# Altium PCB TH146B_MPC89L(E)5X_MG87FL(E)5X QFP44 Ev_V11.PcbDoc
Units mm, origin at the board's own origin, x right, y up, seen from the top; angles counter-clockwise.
Board outline 72.39 x 53.59 mm, 2 copper layers (Top Layer, Bottom Layer); 46 components, 63 nets, 266 pads, 114 vias.
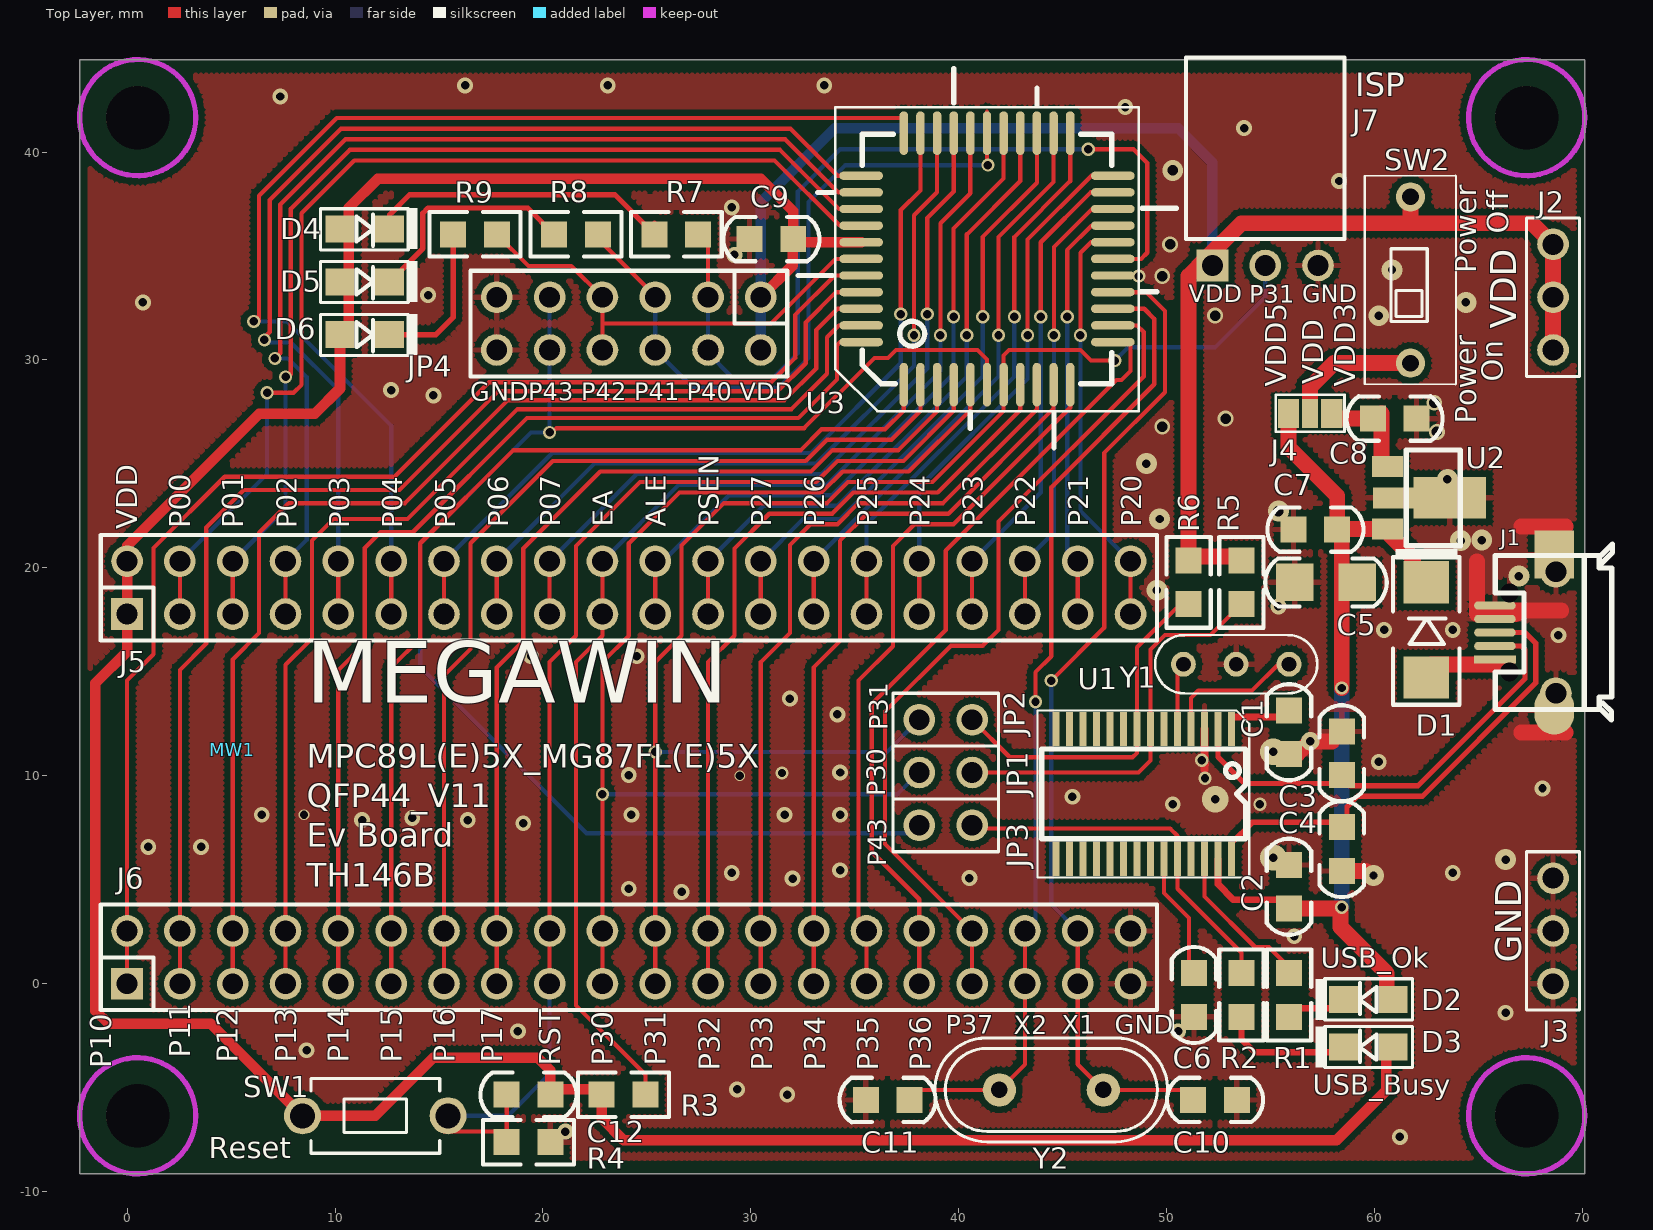
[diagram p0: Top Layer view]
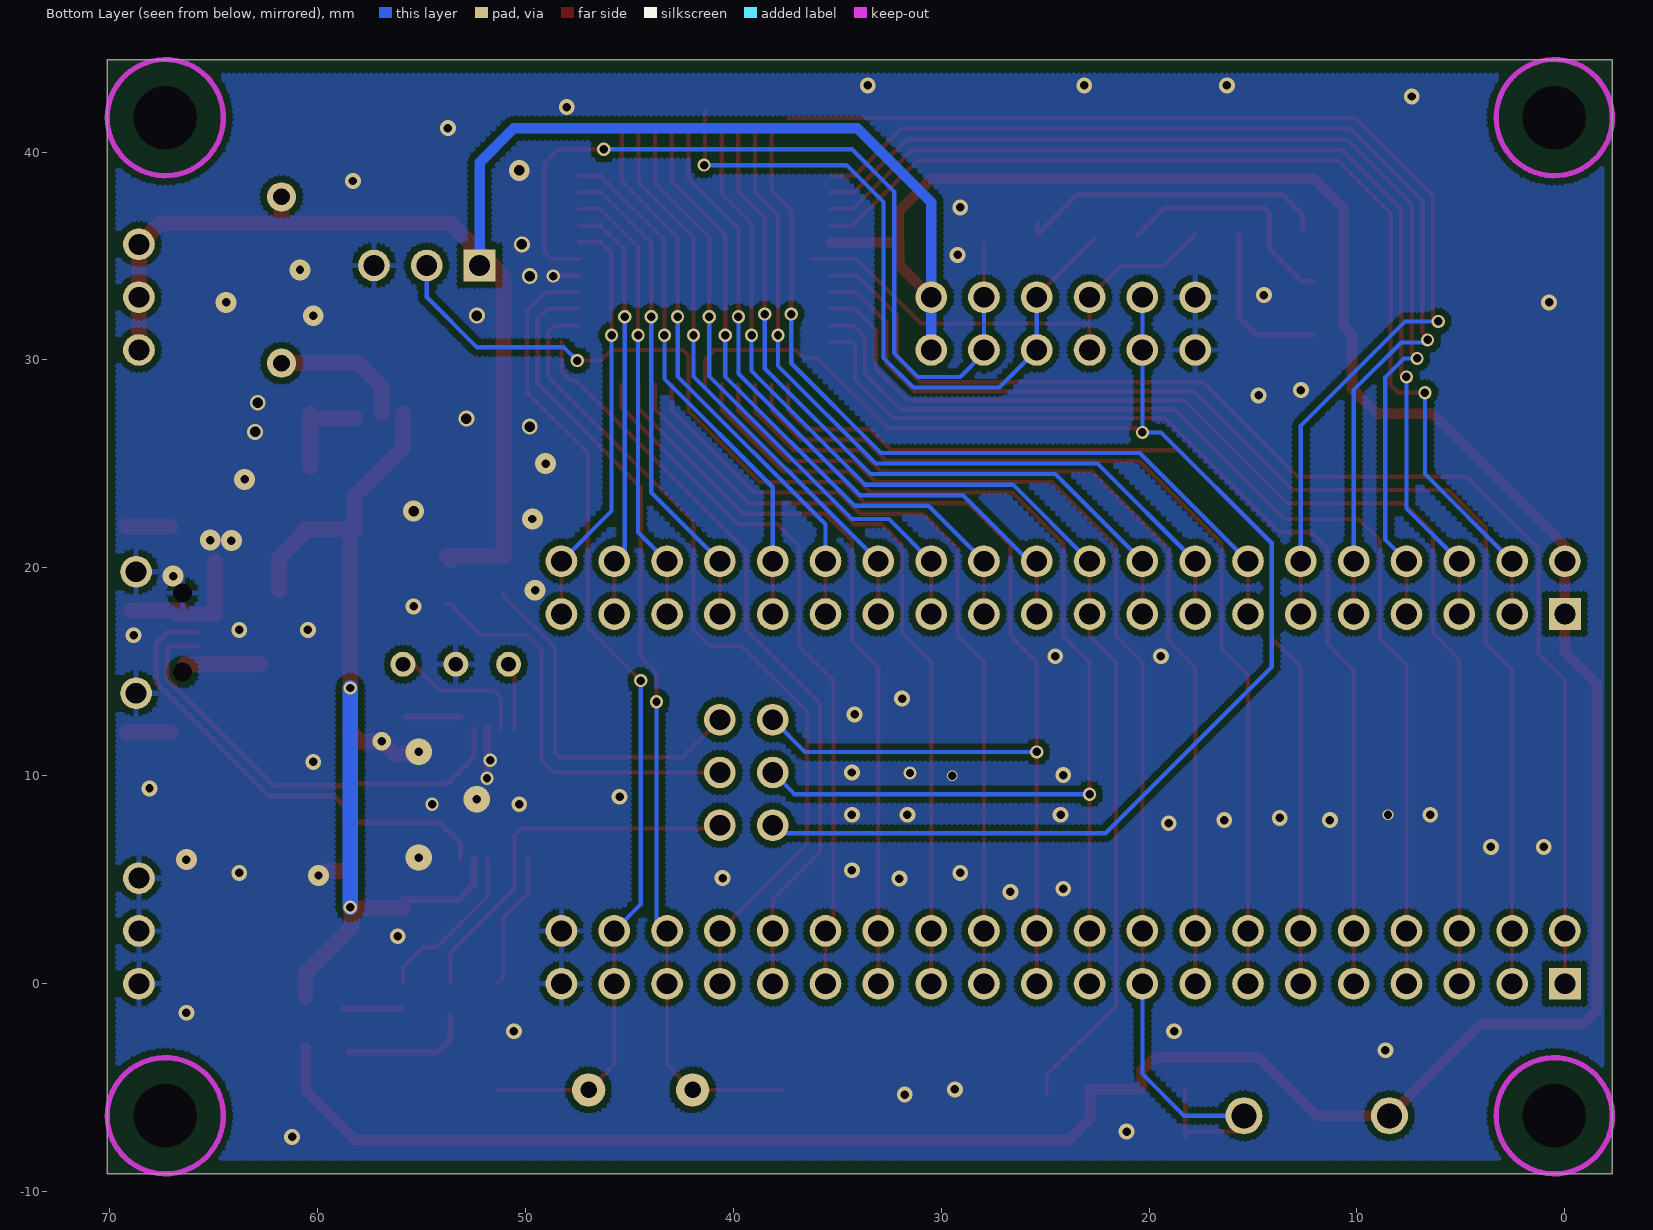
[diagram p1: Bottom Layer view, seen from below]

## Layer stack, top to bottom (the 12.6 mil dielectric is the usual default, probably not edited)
Top Layer: signal copper 0.0356
Dielectric: dielectric 0.32, FR-4, Dk 4.8
Bottom Layer: signal copper 0.0356

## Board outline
-2.286,-9.144 70.104,-9.144 70.104,44.45 -2.286,44.45

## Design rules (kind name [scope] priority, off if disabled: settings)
Clearance 12 [All] p1 off: gap=0.305
Clearance 10 [All] p2 off: gap=0.254
Clearance 6 [All] p3: gap=0.152
ComponentClearance [All] p1 off: gap=0.254 collisioncheckmode=3 verticalgap=0.254 showdistances=FALSE
HoleSize [All] p1: absolutevalues=TRUE maxlimit=12.7 minlimit=0.025 maxpercent=80.000 minpercent=20.000
MinimumSolderMaskSliver [All] p1 off: minsoldermaskwidth=0.254
PolygonConnect VIA [ISVIA] p1: connectstyle=Direct reliefconductorwidth=0.254 reliefentries=4 polygonreliefangle="90 Angle"
PolygonConnect [All] p2: connectstyle=Relief reliefconductorwidth=0.254 reliefentries=4 polygonreliefangle="90 Angle"
RoomDefinition "TH146B_MPC89L(E)5X_MG87FL(E)5X QFP44 Ev_V10" [InComponentClass('TH146B_MPC89L(E)5X_MG87FL(E)5X QFP44 Ev_V10')] p1: confinementstyle=ConfineIn formatcopy=TRUE lockcomponents=FALSE outline -8.636,-13.208 74.549,-13.208 74.549,49.276 -8.636,49.276
RoutingVias [All] p1: holewidth=0.406 width=0.635 viastyle="Through Hole" minholewidth=0.406 minwidth=0.61 maxholewidth=0.711 maxwidth=1.27
SilkToSilkClearance [All] p1 off: silktosilkclearance=0.254
SilkscreenOverComponentPads [All] p1 off: minsilkscreentomaskgap=0.254
SolderMaskExpansion [All] p1 off: expansion=0.102
Width [All] p1: maxlimit=5.08 minlimit=0.152 preferedwidth=0.254
23 further rules are at their usual default settings.

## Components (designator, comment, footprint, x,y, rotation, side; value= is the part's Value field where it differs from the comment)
C1 "4.7uF" 0805C 55.88,12.099 r270 top
C2 "0.1uF" 0805C 55.88,4.665 r270 top
C3 "15pF" 0805C 58.42,11.083 r90 top
C4 "15pF" 0805C 58.42,6.477 r270 top
C5 "4.7uF" 1206C 57.658,19.304 r180 top
C6 "0.1uF" 0805C 51.308,-0.542 r90 top
C7 "0.1uF" 0805C 57.15,21.844 r180 top
C8 "4.7uF" 0805C 60.96,27.178 r0 top
C9 "0.1uF" 0805C 30.988,35.814 r180 top
C10 "30p" 0805C 52.324,-5.588 r0 top
C11 "30p" 0805C 36.576,-5.588 r180 top
C12 "1u" 0805C 19.304,-5.334 r180 top
D1 "1N5817" D5817_SMD_1 62.484,17.018 r270 top
D2 "Yellow" 0805D 59.69,-0.762 r180 top
D3 "RED" 0805D 59.69,-3.048 r180 top
D4 "Green" 0805D 11.43,36.297 r0 top
D5 "RED" 0805D 11.43,33.757 r0 top
D6 "Green" 0805D 11.43,31.217 r0 top
J1 "Micro USB母座" JACK_USB_SMD290X220P065 65.786,16.891 r180 top
J2 "*" PS3P254 68.58,30.48 r90 top
J3 "*" PS3P254 68.58,0 r90 top
J4 "*" JUMP3_SMD 56.896,27.432 r0 top
J5 "CON40A" PS20X2P254 0,17.78 r0 top locked
J6 "CON40A" PS20X2P254 0,0 r0 top
J7 "*" PS3P254f_90 52.197,34.544 r0 top
JP1 "JUMPER2" PS2P254 38.1,10.16 r0 top
JP2 "JUMPER2" PS2P254 38.1,12.7 r0 top
JP3 "JUMPER2" PS2P254 38.1,7.62 r0 top
JP4 "CON6X2" PS6X2P254 30.48,33.02 r180 top
MW1 "MW-A4" MEGAWIN_T 5.059,11.253 r0 top
R1 "1K" 0805R 55.88,-0.542 r270 top
R2 "1K" 0805R 53.594,-0.542 r270 top
R3 "4.7K" 0805R 23.876,-5.334 r0 top
R4 "47K" 0805R 19.304,-7.62 r180 top
R5 "4.7K" 0805R 53.594,19.304 r270 top
R6 "4.7K" 0805R 51.054,19.304 r270 top
R7 "1K" 0805R 26.416,36.043 r180 top
R8 "1K" 0805R 21.59,36.043 r180 top
R9 "1K" 0805R 16.73,36.043 r180 top
SW1 "SW TACT-SPST" SW_T_2P 11.938,-6.35 r180 top
SW2 "-" DIP2_SW 61.722,29.846 r90 top
U1 "MA101_TSSOP28" TSSOP28_170P065 48.891,9.132 r180 top
U2 "AIC1734-33(SOT-89)" SOT89 60.614,23.368 r270 top
U3 "MPC89E53(44-QFP)" QFP44_10X10P080 37.356,28.812 r90 top
Y1 "6MHz" X3P 55.88,15.367 r180 top
Y2 "22.1184MHz" X49U 44.45,-5.105 r180 top

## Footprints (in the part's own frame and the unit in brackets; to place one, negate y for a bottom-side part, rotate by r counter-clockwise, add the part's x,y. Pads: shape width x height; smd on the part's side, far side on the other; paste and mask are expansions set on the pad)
0805C [mm]
  rect 1.25x1.25 smd: 1(-1.05,0) 2(1.05,0)
  silkscreen extent -2.31,-1.07 2.31,1.07
0805D [mm]
  rect 1.4x1.3 smd: 1(-1.192,0) 2(1.192,0)
  silkscreen extent -2.12,-1 2.53,0.98
0805R [mm]
  rect 1.25x1.25 smd: 1(-1.05,0) 2(1.05,0)
  silkscreen extent -2.18,-1.07 2.18,1.07
1206C [mm]
  rect 1.8x1.8 smd: 1(-1.5,0) 2(1.5,0)
  silkscreen extent -2.92,-1.15 2.92,1.16
D5817_SMD_1 [mil]
  rect 80x86.61 smd: 1(90,0) 2(-90,0)
  silkscreen extent -153,-63 142,63
DIP2_SW [mm]
  round 1.4 hole 0.8: 1(0,0) 2(8,0)
  silkscreen extent -1.02,-2.2 9.02,2.2
JACK_USB_SMD290X220P065 [mm]
  rect 1.9x1.8 on Mech2: 0(-2.85,-1.15) 0(-2.85,1.15)
  round 0.8 hole 0.9 unplated: 1(-0.7,1.9) 5(-0.7,-1.9)
  rect 2x0.4 smd: 1(0,1.3)
  oval 2x0.4 smd: 2(0,0.65) 3(0,0) 4(0,-0.65) 5(0,-1.3)
  round 1.524 hole 1: 5(-2.931,2.921) 5(-2.931,-2.921)
  oval 1.9x2.3 smd: 5(-2.85,3.75)
  rect 1.9x2.3 smd: 5(-2.85,-3.75)
  silkscreen extent -5.65,-4.25 -0.01,4.2
JUMP3_SMD [mil]
  rect 40x55 smd: 1(-41,0) 3(41,0)
  rect 30x55 smd: 2(0,0)
  silkscreen extent -65,-35 65,35
MEGAWIN_T [mm]
PS2P254 [mil]
  round 60 hole 39.37: 1(0,0) 2(100,0)
  silkscreen extent -50,-50 150,50
PS3P254 [mil]
  round 60 hole 39.37: 1(0,0) 2(100,0) 3(200,0)
  silkscreen extent -50,-50 250,50
PS3P254f_90 [mil]
  rect 60x60 hole 39.37: 1(0,0)
  round 60 hole 39.37: 2(100,0) 3(200,0)
  silkscreen extent -50,50 250,394
PS6X2P254 [mil]
  round 60 hole 39.37: 1(0,0) 2(0,100) 3(100,0) 4(100,100) 5(200,0) 6(200,100) 7(300,0) 8(300,100) 9(400,0) 10(400,100) 11(500,0) 12(500,100)
  silkscreen extent -50,-50 550,150
PS20X2P254 [mil]
  rect 60x60 hole 39.37: 1(0,0)
  round 60 hole 39.37: 2(0,100) 3(100,0) 4(100,100) 5(200,0) 6(200,100) 7(300,0) 8(300,100) 9(400,0) 10(400,100) 11(500,0) 12(500,100) 13(600,0) 14(600,100) 15(700,0) 16(700,100) 17(800,0) 18(800,100) 19(900,0) 20(900,100) 21(1000,0) 22(1000,100) 23(1100,0) 24(1100,100) 25(1200,0) 26(1200,100) 27(1300,0) 28(1300,100) 29(1400,0) 30(1400,100) 31(1500,0) 32(1500,100) 33(1600,0) 34(1600,100) 35(1700,0) 36(1700,100) 37(1800,0) 38(1800,100) 39(1900,0) 40(1900,100)
  silkscreen extent -50,-50 1950,150
QFP44_10X10P080 [mm]
  oval 2.1x0.406 smd: 1(0,0) 2(0,-0.8) 3(0,-1.6) 4(0,-2.4) 5(0,-3.2) 6(0,-4) 7(0,-4.8) 8(0,-5.6) 9(0,-6.4) 10(0,-7.2) 11(0,-8) 23(12.1,-8) 24(12.1,-7.2) 25(12.1,-6.4) 26(12.1,-5.6) 27(12.1,-4.8) 28(12.1,-4) 29(12.1,-3.2) 30(12.1,-2.4) 31(12.1,-1.6) 32(12.1,-0.8) 33(12.1,0)
  oval 0.406x2.1 smd: 12(2.05,-10.05) 13(2.85,-10.05) 14(3.65,-10.05) 15(4.45,-10.05) 16(5.25,-10.05) 17(6.05,-10.05) 18(6.85,-10.05) 19(7.65,-10.05) 20(8.45,-10.05) 21(9.25,-10.05) 22(10.05,-10.05) 34(10.05,2.05) 35(9.25,2.05) 36(8.45,2.05) 37(7.65,2.05) 38(6.85,2.05) 39(6.05,2.05) 40(5.25,2.05) 41(4.45,2.05) 42(3.65,2.05) 43(2.85,2.05) 44(2.05,2.05)
  silkscreen extent -3.04,-13.12 15.19,5.08
SOT89 [mm]
  rect 1.016x1.5 smd: 1(-1.5,0) 3(1.5,0)
  rect 2x3.5 smd: 2(0,3)
  rect 1.016x2.6 smd: 2(0,0.6)
  silkscreen extent -2.3,0.9 2.3,3.5
SW_T_2P [mm]
  round 1.778 hole 1.2: 1(-3.5,0) 2(3.5,0)
  silkscreen extent -3.1,-1.8 3.1,1.8
TSSOP28_170P065 [mil]
  rect 13x65 smd: 1(-166.34,-123) 2(-140.75,-123) 3(-115.16,-123) 4(-89.57,-123) 5(-63.98,-123) 6(-38.39,-123) 7(-12.79,-123) 8(12.8,-123) 9(38.39,-123) 10(63.98,-123) 11(89.57,-123) 12(115.16,-123) 13(140.75,-123) 14(166.34,-123) 15(166.34,123) 16(140.75,123) 17(115.16,123) 18(89.57,123) 19(63.98,123) 20(38.39,123) 21(12.8,123) 22(-12.79,123) 23(-38.39,123) 24(-63.98,123) 25(-89.57,123) 26(-115.16,123) 27(-140.75,123) 28(-166.34,123)
  silkscreen extent -200,-158 201,158
X3P [mm]
  round 1.2 hole 0.711: 1(0,0) 2(5.08,0) 3(2.54,0)
  silkscreen extent -1.36,-1.4 6.44,1.4
X49U [mm]
  round 1.6 hole 0.8: 1(-2.5,0) 2(2.5,0)
  silkscreen extent -5.6,-2.5 5.6,2.5

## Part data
C1 C5 C8: library part CAP
C2 C3 C4 C6 C7 C9: library part "CAP NP"
C10 C11: library part "C NP"
C12: library part C
D1: library part DIODE_ZD, "Schottky Diode"
D2 D3 D4 D5 D6: library part LED
J1: library part CON5, "Connector"
J2 J3 J4 J7: library part CON3
R1 R2 R5 R6 R7 R8 R9: library part R_Dup1
R3 R4: library part R
SW2: library part SW-2
U2: library part AIC1734-33(SOT-89)_0
U3: library part MPC89L53(44-QFP)
Y1: library part CRYSTAL_RC
Y2: library part CRYSTAL

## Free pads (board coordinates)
  round 3 hole 3.048 unplated: 0(0.508,-6.35) 0(0.508,41.656) 0(67.31,-6.35) 0(67.31,41.656)

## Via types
v1: diameter 0.762, hole 0.406, Top Layer to Bottom Layer, tented both sides, 53 vias
v2: diameter 0.635, hole 0.406, Top Layer to Bottom Layer, tented both sides, 34 vias
v3: diameter 1, hole 0.406, Top Layer to Bottom Layer, tented both sides, 11 vias
v4: diameter 0.762, hole 0.508, Top Layer to Bottom Layer, tented both sides, 7 vias
v5: diameter 1.27, hole 0.406, Top Layer to Bottom Layer, tented both sides, 3 vias
v6: diameter 1, hole 0.508, Top Layer to Bottom Layer, tented both sides, 2 vias
v7: diameter 0.508, hole 0.406, Top Layer to Bottom Layer, tented both sides, 2 vias
v8: diameter 1.016, hole 0.406, Top Layer to Bottom Layer, tented both sides, 1 vias
v9: diameter 0.889, hole 0.406, Top Layer to Bottom Layer, tented both sides, 1 vias

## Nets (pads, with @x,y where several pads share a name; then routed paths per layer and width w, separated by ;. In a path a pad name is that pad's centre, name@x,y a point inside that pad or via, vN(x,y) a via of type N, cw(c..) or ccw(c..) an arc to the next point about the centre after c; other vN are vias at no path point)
ALE: J5.21 J5.22 U3.27 | length 33.2
  Top Layer w0.203: J5.21 J5.22 ; v2(39.751,32.08) 39.751,36.322 42.156,38.727 U3.27
  Bottom Layer w0.203: J5.22 25.781,20.32 28.956,23.495 33.909,23.495 39.751,29.337 v2(39.751,32.08)
D+: C4.1 J1.3 U1.28 | length 22.6
  Top Layer w0.254: U1.28 53.116,6.761 54.119,7.764 C4.1@58.42,7.764 ; C4.1@58.674,8.001 58.674,8.509 59.182,9.017 62.299,9.017 67.742,14.46 67.742,16.381 67.232,16.891 J1.3
D-: C3.1 J1.2 U1.2 | length 21.3
  Top Layer w0.254: U1.2 52.466,10.907 53.737,9.636 C3.1@58.42,9.636 ; C3.1@58.801,9.525 62.089,9.525 67.234,14.67 67.234,16.074 67.067,16.241 J1.2
GND_POWER: C1.2 C2.1 C3.2 C4.2 C5.2 C6.1 C7.2 C8.2 C9.2 C10.2 C11.2 J1.4 J1.5 J3.1 J3.2 J3.3 J6.39 J6.40 J7.3 JP4.11 JP4.12 R4.1 U1.3 U2.2 U3.16 Y1.3 | length 18.4
  Top Layer w0.254: U3.16 48.633,34.062 v2(48.659,34.036)
  Top Layer w0.381: 51.816,10.312 v2@51.816,10.566 ; U1.3 51.816,10.744 v2@51.816,10.566 ; v2@51.841,10.541 v2@51.816,10.566
  Top Layer w0.762: C1.2 56.286,11.049 v9(56.896,11.659) 57.946,11.659 C3.2 ; C4.2 v3@59.554,5.427 ; 64.919,17.781 65.786,17.781 66.784,17.781 ; 64.919,17.847 64.919,18.191 64.919,20.313 ; 66.511,17.959 68.977,17.959 ; 67.063,12.087 68.636,12.087 69.185,12.087 ; 67.063,21.993 68.636,21.993 69.185,21.993
  other v1: 61.214,-7.366 21.082,-7.112 31.75,-5.334 29.337,-5.08 8.636,-3.2 18.796,-2.286 50.546,-2.286 66.294,-1.397 56.134,2.286 26.67,4.42 24.13,4.572 32.004,5.055 40.513,5.08 29.083,5.334 63.754,5.334 34.29,5.461 1.016,6.579 3.556,6.579 19.05,7.722 11.303,7.874 16.383,7.874 13.716,7.976 6.477,8.128 24.257,8.128 31.623,8.128 34.29,8.128 50.292,8.636 45.466,8.992 68.072,9.398 24.13,10.033 34.29,10.16 60.198,10.668 34.163,12.954 31.877,13.716 19.431,15.748 24.511,15.748 68.834,16.764 60.452,17.018 63.754,17.018 55.372,18.147 14.732,28.296 12.7,28.55 0.762,32.766 14.478,33.122 29.21,35.052 29.083,37.338 58.293,38.608 53.721,41.148 48.006,42.164 7.366,42.672 16.256,43.205 23.114,43.205 33.528,43.205
  other v2: 54.483,8.636 51.841,9.881 31.496,10.135 51.689,10.744
  other v3: 59.944,5.207 66.294,5.969 49.53,18.923 64.135,21.311 65.151,21.336 49.657,22.352 63.5,24.257 49.022,25.019 60.198,32.131 64.389,32.766 60.833,34.33
  other v4: 62.992,26.543 49.784,26.797 52.832,27.178 62.865,27.94 52.324,32.131 49.784,34.036 50.165,35.56
  other v5: 55.118,6.071 52.324,8.865 55.118,11.151
  other v6: 55.372,22.733 50.292,39.116
  other v7: 8.509,8.128 29.464,10.008
  other v8: 66.936,19.602
MA101_RX: JP2.2 R6.2 U1.8 | length 17.4
  Top Layer w0.203: JP2.2 42.447,10.893 48.358,10.893 48.566,11.101 U1.8 48.566,16.181 50.846,18.461 51.054,18.669 R6.2@51.054,18.737
MA101_TX: JP1.2 R5.2 U1.7 | length 19.7
  Top Layer w0.203: JP1.2 48.641,10.16 49.216,10.735 U1.7 49.216,16.069 49.914,16.767 52.098,16.767 53.59,18.258 53.594,18.263 R5.2@53.848,18.263
NEA: J5.19 J5.20 R3.2 U3.29 | length 59.6
  Top Layer w0.203: J5.20 J5.19 22.86,16.739 21.59,15.469 21.59,-1.041 24.926,-4.377 R3.2 ; v2(39.116,31.191) 39.116,36.576 40.556,38.016 U3.29
  Bottom Layer w0.203: J5.20 26.543,24.003 33.655,24.003 39.116,29.464 v2(39.116,31.191)
NetC1_1: C1.1 U1.1 | length 2.6
  Top Layer w0.33: U1.1@53.116,12.827 C1.1@55.719,12.827
NetC6_2: C6.2 U1.23 | length 6.6
  Top Layer w0.203: U1.23 49.866,4.363 51.071,3.158 51.071,0.508 51.071,0.271 C6.2@51.308,0.034
NetD1_1: D1.1 J1.1 | length 3.6
  Top Layer w0.762: D1.1@62.738,15.36 65.786,15.36 J1.1@66.35,15.36
NetD2_2: D2.2 R1.2 | length 2.7
  Top Layer w0.305: R1.2@55.982,-1.186 58.498,-1.186 D2.2@58.708,-1.186
NetD3_2: D3.2 R2.2 | length 6.2
  Top Layer w0.305: R2.2 53.594,-2.667 54.229,-3.302 D3.2@58.498,-3.302
NetD4_2: D4.2 R7.2 | length 15.2
  Top Layer w0.254: D4.2 12.622,36.98 13.589,37.948 23.461,37.948 R7.2 R7.2@25.366,36.585
NetD5_2: D5.2 R8.2 | length 11.4
  Top Layer w0.254: D5.2@12.114,33.757 D5.2 14.224,35.359 14.224,37.059 14.478,37.313 19.27,37.313 R8.2
NetD6_2: D6.2 R9.2 | length 7.9
  Top Layer w0.254: D6.2@12.114,31.217 D6.2 14.859,31.217 15.68,32.038 R9.2
NetJ4_2: J4.2 SW2.1 | length 6.6
  Top Layer w0.762: J4.2 56.896,28.702 58.04,29.846 SW2.1
NetU1_4: U1.4 Y1.1 | length 6.9
  Top Layer w0.203: U1.4 51.166,13.749 51.514,14.097 54.102,14.097 55.372,15.367 Y1.1
NetU1_5: U1.5 Y1.2 | length 3.2
  Top Layer w0.203: U1.5 50.516,15.083 Y1.2
P00: J5.3 J5.4 U3.37 | length 51.7
  Top Layer w0.203: J5.3 J5.4 ; v2(6.731,28.423) 8.001,28.423 8.382,28.804 8.382,37.059 10.922,39.599 31.14,39.599 34.277,36.462 U3.37
  Bottom Layer w0.203: J5.4 6.731,24.511 v2(6.731,28.423)
P01: J5.5 J5.6 U3.36 | length 50.2
  Top Layer w0.203: J5.5 J5.6 ; v2@7.874,29.312 7.874,37.269 10.712,40.107 31.394,40.107 34.239,37.262 U3.36
  Bottom Layer w0.203: J5.6 7.62,22.86 v2(7.62,29.185)
P02: J5.7 J5.8 U3.35 | length 51.5
  Top Layer w0.203: v2(7.112,30.074) 7.366,30.328 7.366,37.479 10.501,40.615 31.648,40.615 34.201,38.062 U3.35 ; J5.7 J5.8
  Bottom Layer w0.203: v2(7.112,30.074) 7.747,30.074 8.636,29.185 8.636,21.336 J5.8
P03: J5.9 J5.10 U3.34 | length 52.9
  Top Layer w0.203: v2@6.54,31.026 6.858,31.344 6.858,37.69 10.291,41.123 31.902,41.123 34.163,38.862 U3.34 ; J5.9 J5.10
  Bottom Layer w0.203: v2@6.604,30.836 7.874,30.836 10.16,28.55 J5.10
  other v2: 6.604,30.963
P04: J5.11 J5.12 U3.33 | length 56.9
  Top Layer w0.203: v2(6.096,31.852) 6.35,32.106 ; v2@6.35,31.852 6.35,32.106 ; 6.35,32.233 6.35,32.487 ; J5.11 J5.12 ; U3.33@37.338,41.631 10.08,41.631 6.35,37.9 6.35,32.487 ; 6.35,32.106 6.35,32.487
  Bottom Layer w0.203: v2(6.096,31.852) 7.695,31.852 12.7,26.847 J5.12
P05: J5.13 J5.14 U3.32 | length 39.9
  Top Layer w0.203: J5.13 J5.14 ; v2(37.211,32.207) 37.211,37.211 38.156,38.156 U3.32
  Bottom Layer w0.203: J5.14 20.447,25.527 32.893,25.527 37.211,29.845 v2(37.211,32.207)
P06: J5.15 J5.16 U3.31 | length 38.2
  Top Layer w0.203: J5.15 J5.16 ; v2(37.846,31.191) 37.846,36.957 38.956,38.067 U3.31
  Bottom Layer w0.203: J5.16 22.479,25.019 33.147,25.019 37.846,29.718 v2(37.846,31.191)
P07: J5.17 J5.18 U3.30 | length 36.4
  Top Layer w0.203: J5.17 J5.18 ; v2(38.481,32.207) 38.481,36.83 39.756,38.105 U3.30
  Bottom Layer w0.203: J5.18 24.511,24.511 33.401,24.511 38.481,29.591 v2(38.481,32.207)
P10: J6.1 J6.2 U3.40 | length 62.2
  Top Layer w0.203: J6.1 J6.2 0,14.58 1.27,15.85 1.27,20.955 4.699,24.384 12.852,24.384 17.399,28.931 30.963,28.931 32.131,30.099 32.131,32.156 34.036,34.062 U3.40
P11: J6.3 J6.4 U3.41 | length 61.3
  Top Layer w0.203: J6.3 J6.4 2.54,15.088 3.81,16.358 3.81,18.263 ; 3.81,16.739 3.81,18.263 ; U3.41 34.1,33.262 32.639,31.801 32.639,29.845 31.293,28.499 17.856,28.499 13.106,23.749 5.613,23.749 3.81,21.946 3.81,18.263
P12: J6.5 J6.6 U3.42 | length 57.9
  Top Layer w0.203: J6.5 J6.6 5.08,15.596 6.35,16.866 6.35,18.136 ; 6.35,16.993 6.35,18.136 ; U3.42 34.163,32.462 33.147,31.445 33.147,29.591 31.623,28.067 18.313,28.067 13.36,23.114 7.772,23.114 6.35,21.692 6.35,18.136
P13: J6.7 J6.8 U3.43 | length 53.9
  Top Layer w0.203: J6.7 J6.8 7.62,15.342 8.89,16.612 8.89,17.755 ; 8.89,17.374 8.89,17.755 ; U3.43 34.227,31.662 33.655,31.09 33.655,29.337 31.953,27.635 18.771,27.635 13.487,22.352 9.931,22.352 8.89,21.311 8.89,17.755
P14: J6.9 J6.10 U3.44 | length 52.3
  Top Layer w0.203: J6.9 J6.10 10.16,15.088 11.43,16.358 11.43,18.517 ; 11.43,16.612 11.43,18.517 ; U3.44 34.291,30.862 34.138,30.709 34.138,29.058 32.283,27.203 19.228,27.203 13.741,21.717 12.192,21.717 11.43,20.955 11.43,18.517
P15: J6.11 J6.12 U3.1 | length 48.9
  Top Layer w0.203: J6.11 J6.12 12.7,15.215 14.097,16.612 14.097,21.184 18.567,25.654 32.385,25.654 33.401,26.67 36.449,26.67 37.356,27.577 U3.1
P16: J6.13 J6.14 U3.2 | length 47.8
  Top Layer w0.203: J6.13 J6.14 15.24,14.834 16.51,16.104 16.51,17.501 ; 16.51,16.993 16.51,17.501 ; U3.2 38.156,27.559 36.759,26.162 33.655,26.162 32.639,25.146 20.472,25.146 16.51,21.184 16.51,17.501
P17: J6.15 J6.16 U3.3 | length 48.1
  Top Layer w0.203: J6.15 J6.16 17.78,15.215 19.05,16.485 19.05,18.39 ; 19.05,16.739 19.05,18.39 ; 38.956,27.711 U3.3 38.956,27.526 37.084,25.654 33.909,25.654 32.893,24.638 22.758,24.638 19.05,20.93 19.05,18.39
P20: J5.39 J5.40 U3.18 | length 20.1
  Top Layer w0.203: v2(45.847,31.191) 45.847,35.154 46.355,35.662 U3.18 ; J5.39 J5.40
  Bottom Layer w0.203: v2(45.847,31.191) 45.847,22.733 J5.40
P21: J5.37 J5.38 U3.19 | length 20.4
  Top Layer w0.203: v2(45.212,32.08) 45.212,35.281 46.393,36.462 U3.19 ; J5.37 J5.38
  Bottom Layer w0.203: v2(45.212,32.08) 45.212,20.828 J5.38
P22: J5.35 J5.36 U3.20 | length 21.8
  Top Layer w0.203: J5.35 J5.36 ; v2(44.577,31.191) 44.577,35.433 46.406,37.262 U3.20
  Bottom Layer w0.203: J5.36 44.577,21.717 v2(44.577,31.191) v2@44.582,31.186
P23: J5.33 J5.34 U3.21 | length 23.7
  Top Layer w0.203: J5.33 J5.34 ; v2(43.942,32.08) 43.942,35.662 46.342,38.062 U3.21
  Bottom Layer w0.203: J5.34 43.942,23.622 v2(43.942,32.08)
P24: J5.31 J5.32 U3.22 | length 25.5
  Top Layer w0.203: J5.31 J5.32 ; v2(43.307,31.191) 43.307,35.789 46.38,38.862 U3.22
  Bottom Layer w0.203: J5.32 38.1,23.876 43.307,29.083 v2(43.307,31.191)
P25: J5.29 J5.30 U3.23 | length 27.2
  Top Layer w0.203: J5.29 J5.30 ; v2(42.672,32.08) 42.672,35.916 45.356,38.6 U3.23
  Bottom Layer w0.203: J5.30 35.56,22.098 42.672,29.21 v2(42.672,32.08)
P26: J5.27 J5.28 U3.24 | length 27.9
  Top Layer w0.203: J5.27 J5.28 ; v2(41.91,31.191) 41.91,35.916 44.556,38.562 U3.24
  Bottom Layer w0.203: J5.28 41.91,29.21 v2(41.91,31.191)
P27: J5.25 J5.26 U3.25 | length 29.7
  Top Layer w0.203: J5.25 J5.26 ; v2(41.148,32.08) 41.148,35.916 43.756,38.524 U3.25
  Bottom Layer w0.203: J5.26 32.512,22.352 34.29,22.352 41.148,29.21 v2(41.148,32.08)
P30_RXD: J6.19 J6.20 JP1.1 U3.5 | length 58.5
  Top Layer w0.203: J6.19@22.86,0.229 J6.20 v2(22.86,9.119) 22.86,15.469 24.13,16.739 24.13,18.136 ; 24.13,17.12 24.13,18.136 ; U3.5 40.556,27.602 37.592,24.638 34.417,24.638 33.401,23.622 26.568,23.622 24.13,21.184 24.13,18.136
  Bottom Layer w0.203: v2(22.86,9.119) 37.059,9.119 JP1.1
P31_TXD: J6.21 J6.22 J7.2 JP2.1 U3.7 | length 71.9
  Top Layer w0.203: J6.21@25.4,0.229 J6.22 v2(25.4,11.151) 25.4,15.469 26.67,16.739 26.67,17.501 ; 26.67,16.866 26.67,17.501 ; v2(47.498,29.972) 46.355,29.972 45.847,30.48 42.418,30.48 42.156,30.218 U3.7 42.156,27.551 38.735,24.13 34.671,24.13 33.655,23.114 28.702,23.114 26.67,21.082 26.67,17.501
  Bottom Layer w0.203: v2(25.4,11.151) 36.551,11.151 JP2.1 ; v2(47.498,29.972) 48.133,30.607 52.324,30.607 54.737,33.02 J7.2
P32: J6.23 J6.24 U3.8 | length 39
  Top Layer w0.203: J6.23@27.94,0.229 J6.24 27.94,15.469 29.21,16.739 29.21,20.93 30.886,22.606 33.909,22.606 34.925,23.622 38.989,23.622 42.956,27.589 U3.8
P33: J6.25 J6.26 U3.9 | length 37.2
  Top Layer w0.203: J6.25@30.48,0.229 J6.26 30.48,15.469 31.877,16.866 31.877,21.1 32.875,22.098 34.163,22.098 35.179,23.114 39.243,23.114 43.756,27.627 U3.9
P34: J6.27 J6.28 U3.10 | length 35.7
  Top Layer w0.203: J6.27@33.02,0.229 J6.28 33.02,15.215 34.29,16.485 34.29,21.311 35.585,22.606 39.497,22.606 44.556,27.665 U3.10
P35: J6.29 J6.30 U3.11 | length 33.7
  Top Layer w0.203: J6.30@35.052,2.794 35.179,2.921 35.179,14.58 36.83,16.231 36.83,21.057 37.871,22.098 39.751,22.098 45.356,27.703 U3.11 ; J6.29@35.56,0.229 J6.30
P36: J6.31 J6.32 U3.12 | length 36.9
  Top Layer w0.203: J6.31@38.1,0.229 J6.32 38.1,4.064 35.814,6.35 35.814,13.462 39.37,17.018 39.37,20.828 47.575,29.033 47.829,29.033 48.26,29.464 U3.12@48.26,30.861
P37: J6.33 J6.34 U3.13 | length 40.8
  Top Layer w0.203: J6.33@40.64,0.229 J6.34 36.457,6.723 36.457,13.089 39.624,16.256 41.148,16.256 41.91,17.018 41.91,19.533 ; 41.91,19.279 41.91,19.533 ; U3.13 48.577,31.662 48.895,31.344 48.895,29.21 41.91,22.225 41.91,19.533
P40: JP4.3 JP4.4 R7.1 U3.17 | length 43.5
  Top Layer w0.203: JP4.3 R7.1@27.94,35.569 ; v2(46.228,40.132) 48.405,40.132 49.062,39.475 49.062,35.154 48.77,34.862 U3.17 U3.17@48.298,34.862
  Bottom Layer w0.203: JP4.4@27.94,29.972 JP4.4@27.94,30.328 ; JP4.3 JP4.4 JP4.4@27.94,30.328 ; v2(46.228,40.132) 34.29,40.132 32.258,38.1 32.258,30.328 31.115,29.185 29.083,29.185 JP4.4@27.94,30.328
P41: JP4.5 JP4.6 R8.1 U3.28 | length 34.6
  Top Layer w0.203: R8.1@22.64,35.831 25.4,33.071 JP4.5 ; U3.28@41.356,41.939 U3.28 41.356,39.416 v2(41.402,39.37)
  Bottom Layer w0.203: JP4.5 JP4.6 27.203,28.677 31.344,28.677 32.766,30.099 32.766,37.592 34.544,39.37 v2(41.402,39.37)
P42: JP4.7 JP4.8 R9.1 U3.39 | length 23.5
  Top Layer w0.203: R9.1 19.304,34.519 21.361,34.519 JP4.7 22.86,31.75 ; JP4.8 22.86,31.75 ; U3.39@36.233,34.862 U3.39 34.074,34.862 30.962,31.75 22.86,31.75
P43: JP3.1 JP4.9 JP4.10 U3.6 | length 72.7
  Top Layer w0.203: v2@20.32,26.391 20.383,26.454 20.65,26.721 32.563,26.721 35.941,30.099 36.601,30.099 36.982,30.48 40.894,30.48 41.356,30.018 U3.6 U3.6@41.356,28.75
  Bottom Layer w0.203: v2@20.32,26.391 v2(20.32,26.518) ; JP4.9 JP4.10 v2(20.32,26.518) ; JP3.1 37.719,7.239 22.098,7.239 14.097,15.24 14.097,21.183 19.431,26.518 v2(20.32,26.518)
PSEN: J5.23 J5.24 U3.26 | length 31.4
  Top Layer w0.203: J5.23 J5.24 ; v2(40.386,31.191) 40.386,36.043 42.956,38.613 U3.26
  Bottom Layer w0.203: J5.24 30.607,22.987 34.163,22.987 40.386,29.21 v2(40.386,31.191)
RST: C12.2 J6.17 J6.18 R4.2 SW1.1 U3.4 | length 58.9
  Top Layer w0.203: SW1.1@15.24,-7.112 15.438,-7.112 R4.2@18.056,-7.112 ; R4.2@18.254,-7.366 C12.2 C12.2@18.254,-5.08 ; J6.17 J6.18 20.32,15.469 21.59,16.739 21.59,21.057 24.663,24.13 33.147,24.13 34.163,25.146 37.338,25.146 39.756,27.564 U3.4
  Bottom Layer w0.203: SW1.1 18.313,-6.35 20.32,-4.343 J6.17
USB_BUSY: JP3.2 R2.1 U1.24 | length 20.3
  Top Layer w0.203: JP3.2@40.792,7.468 43.815,7.468 ; 42.164,7.468 43.815,7.468 ; U1.24@50.516,6.431 U1.24 ; R2.1@53.594,0.034 R2.1 53.594,1.494 50.516,4.572 U1.24 ; 43.815,7.468 50.165,7.468 50.516,7.117 U1.24
USB_OK: R1.1 U1.26 | length 8
  Top Layer w0.203: U1.26 51.816,4.191 54.254,1.753 54.923,1.753 55.88,0.796 R1.1 R1.1@55.88,0.034
VDD: C9.1 C12.1 D3.1 D4.1 D5.1 D6.1 J2.1 J2.2 J2.3 J5.1 J5.2 J7.1 JP4.1 JP4.2 R3.1 R5.1 R6.1 SW1.2 SW2.2 U3.38 | length 229.5
  Top Layer w0.508: 3.302,-1.93 -0.889,-1.93 ; R3.1 22.826,-6.468 23.876,-7.518 58.166,-7.518 60.55,-5.135 D3.1@60.55,-3.048 ; R3.1@22.86,-5.842 22.86,-5.334 22.86,-5.08 22.826,-5.08 20.354,-5.08 20.354,-4.157 19.753,-3.556 14.732,-3.556 11.938,-6.35 SW1.2 4.018,-1.93 -0.889,-1.93 ; JP4.1 32.004,34.544 C9.1@32.004,35.814 ; C9.1 32.038,37.152 30.48,38.71 12.065,38.71 10.668,37.313 10.668,36.297 10.668,33.757 10.668,31.646 D6.1 10.238,28.628 9.017,27.407 6.35,27.407 0,21.057 J5.2 J5.1 0,15.977 -1.524,14.453 -1.524,-1.295 -0.889,-1.93 ; C9.1@32.131,35.662 U3.38
  Top Layer w0.762: R5.1 R5.1@53.594,20.549 ; R5.1@53.789,20.549 R5.1@53.594,20.549 ; 61.722,36.703 SW2.2 ; J2.1 J2.2 J2.3 67.564,36.576 53.594,36.576 51.88,34.861 51.054,34.036 51.054,20.549 R5.1@53.594,20.549
  Bottom Layer w0.508: JP4.2 JP4.1 30.48,37.592 34.036,41.148 50.546,41.148 52.197,39.497 J7.1
VDD3: C8.1 J4.3 U2.1 | length 4.3
  Top Layer w0.762: J4.3@58.166,27.178 C8.1 ; U2.1@60.325,24.868 60.325,27.178 C8.1@60.325,27.432
VDD5: C2.2 C5.1 C7.1 D1.2 D2.1 J4.1 U1.27 U2.3 | length 43.3
  Top Layer w0.33: U1.27 52.466,4.786 53.213,4.039 C2.2@55.88,4.039
  Top Layer w0.762: J4.1 55.855,25.806 58.2,23.461 C7.1 ; C2.2 58.352,3.615 58.352,2.735 60.579,0.508 D2.1@60.579,-0.635 ; v2(58.42,14.224) 58.42,19.304 58.42,21.624 C7.1 ; U2.3 U2.3@60.452,21.868 ; D1.2@61.849,18.923 61.849,19.304 61.849,20.471 60.533,21.787 U2.3@60.452,21.868 ; C7.1 58.224,21.868 U2.3@60.452,21.868
  Bottom Layer w0.762: v2(58.42,3.683) v2(58.42,14.224)
X1: C10.1 J6.37 J6.38 U3.15 Y2.1 | length 48
  Top Layer w0.203: v2@44.45,14.453 v2(44.45,14.58) 46.99,17.12 46.99,25.527 49.911,28.448 49.911,32.36 49.009,33.262 U3.15 ; J6.38 J6.37 45.72,-3.875 Y2.1 C10.1@51.274,-5.105
  Bottom Layer w0.203: v2@44.45,14.453 44.45,3.81 J6.38
X2: C11.1 J6.35 J6.36 U3.14 Y2.2 | length 46.5
  Top Layer w0.203: C11.1@37.626,-5.105 Y2.2 43.18,-3.875 J6.35 J6.36 ; v2(43.688,13.564) 43.688,14.986 44.45,15.748 44.45,23.876 49.403,28.829 49.403,31.979 48.92,32.462 U3.14
  Bottom Layer w0.203: J6.36@43.688,2.54 v2(43.688,13.564)
pads on no net: J1.0 U1.6 U1.9 U1.10 U1.11 U1.12 U1.13 U1.14 U1.15 U1.16 U1.17 U1.18 U1.19 U1.20 U1.21 U1.22 U1.25

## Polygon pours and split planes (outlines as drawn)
GND_POWER on Top Layer "Bottom Layer-No Net" (hatched 90Degree grid 0.254 track 0.254, remove dead copper, pour order 1001): -1.778,-8.407 69.596,-8.407 69.596,43.688 -1.778,43.688
GND_POWER on Bottom Layer "Bottom Layer-No Net" (hatched 90Degree grid 0.254 track 0.254, remove dead copper, pour order 1001): -1.778,-8.407 69.596,-8.407 69.596,43.688 -1.778,43.688

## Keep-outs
Keep-Out Layer:
  circle w0.254: c0.508,-6.35 r2.794
  circle w0.254: c67.31,-6.35 r2.794
  circle w0.254: c67.31,41.656 r2.794
  circle w0.254: c0.508,41.656 r2.794

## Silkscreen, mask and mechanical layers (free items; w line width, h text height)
Top Overlay:
  text "ISP" at 59.055,42.672 h1.14
  text "Off" at 66.421,36.068 h1.02 r90
  text "Power" at 64.897,34.163 h1.02 r90
  text "VDD" at 51.054,32.766 h0.84
  text "GND" at 56.515,32.766 h0.84
  text "P31" at 53.975,32.741 h0.84
  text "VDD" at 66.802,31.496 h1.27 r90
  text "On" at 66.167,28.956 h1.02 r90
  text "VDD" at 57.531,28.829 h1.02 r90
  text "VDD5" at 55.753,28.702 h1.02 r90
  text "VDD3" at 59.055,28.702 h1.02 r90
  text "P43" at 19.304,28.067 h0.84
  text "P42" at 21.844,28.067 h0.84
  text "P41" at 24.384,28.067 h0.84
  text "P40" at 26.924,28.067 h0.84
  text "VDD" at 29.464,28.067 h0.84
  text "GND" at 16.513,28.044 h0.9
  text "Power" at 64.897,26.924 h1.02 r90
  text "P07" at 20.828,21.971 h0.97 r90
  text "EA" at 23.368,21.971 h0.97 r90
  text "ALE" at 25.908,21.971 h0.97 r90
  text "PSEN" at 28.448,21.971 h0.97 r90
  text "P27" at 30.988,21.971 h0.97 r90
  text "P26" at 33.528,21.971 h0.97 r90
  text "P25" at 36.068,21.971 h0.97 r90
  text "P24" at 38.608,21.971 h0.97 r90
  text "P23" at 41.148,21.971 h0.97 r90
  text "P22" at 43.688,21.971 h0.97 r90
  text "P21" at 46.228,21.971 h0.97 r90
  text "P20" at 48.768,21.971 h0.97 r90
  text "P06" at 18.339,21.946 h0.97 r90
  text "P00" at 3.048,21.895 h1.02 r90
  text "P01" at 5.588,21.895 h1.02 r90
  text "P02" at 8.153,21.895 h0.97 r90
  text "P03" at 10.693,21.895 h0.97 r90
  text "P04" at 13.233,21.895 h0.97 r90
  text "P05" at 15.773,21.895 h0.97 r90
  text "VDD" at 0.483,21.869 h1.02 r90
  text "P31" at 36.576,12.192 h0.89 r90
  text "MPC89L(E)5X_MG87FL(E)5X" at 8.636,10.389 h1.14
  text "P30" at 36.457,9.017 h0.89 r90
  text "QFP44_V11" at 8.636,8.484 h1.14
  text "Ev Board" at 8.636,6.579 h1.14
  text "P43" at 36.505,5.659 h0.89 r90
  text "TH146B" at 8.636,4.674 h1.14
  text "GND" at 67.056,1.016 h1.27 r90
  text "USB_Ok" at 57.404,0.762 h0.97
  text "P37" at 39.37,-2.413 h0.89
  text "X1" at 44.958,-2.413 h0.9
  text "GND" at 47.498,-2.413 h0.9
  text "X2" at 42.647,-2.438 h0.89
  text "P11" at 3.048,-3.556 h1.02 r90
  text "P12" at 5.334,-3.81 h1.02 r90
  text "P13" at 8.128,-3.81 h1.02 r90
  text "P14" at 10.668,-3.81 h1.02 r90
  text "P15" at 13.208,-3.81 h1.02 r90
  text "P16" at 15.748,-3.81 h1.02 r90
  text "P17" at 18.034,-3.81 h1.02 r90
  text "RST" at 20.828,-3.937 h1.02 r90
  text "P30" at 23.368,-3.937 h1.02 r90
  text "P31" at 25.908,-3.937 h1.02 r90
  text "P10" at -0.762,-4.064 h1.02 r90
  text "P32" at 28.499,-4.191 h1.02 r90
  text "P33" at 31.039,-4.191 h1.02 r90
  text "P34" at 33.579,-4.191 h1.02 r90
  text "P35" at 36.119,-4.191 h1.02 r90
  text "P36" at 38.659,-4.191 h1.02 r90
  text "USB_Busy" at 57.023,-5.334 h0.97
  text "Reset" at 3.937,-8.382 h1.02
Mechanical 1:
  the board outline again, w0.33

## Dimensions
-2.286,-9.144 to -2.286,44.45 on Top Overlay
-2.286,-9.144 to 70.104,-9.144 on Top Overlay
